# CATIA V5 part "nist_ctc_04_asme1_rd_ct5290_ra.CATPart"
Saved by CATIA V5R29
Part number: 2012_CTC_04_ASME1_V5R29_RD
Revision: D
Nomenclature: NIST PMI Test Case 4 Complex Model
Description: Complex Test Case 04 Rev C
Property "Modeled By": "Rich Eckenrode, RECON Services Incorporated - Revised by DS"
Property "CAGE Code": "64JW1"
Property "Company": "RECON Services Incorporated"
Bounding box of the stored display mesh (mm): x -250 to 250, y 0 to 780, z -134.842 to 40
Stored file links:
  E:\users\dgn\TPS V5\Import-export annotations\Step\PMI representation 2015\NIST UC\CTC\nist_ctc_04_asme1_ct5210_rd - V5R29.CATPart
  C:\Program Files\Dassault Systemes\B21\win_b64\reffiles\standard\MetricThinPitch.txt
  C:\Program Files\Dassault Systemes\B21\win_b64\reffiles\standard\MetricThickPitch.txt
  E:\users\dgn\TPS V5\Import-export annotations\Step\PMI representation 2015\NIST UC\CTC\nist_ctc_04_asme1_ct5210_rd.CATPart
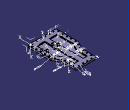
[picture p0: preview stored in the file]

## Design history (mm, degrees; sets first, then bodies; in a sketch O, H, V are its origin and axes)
TTRSSet1
AxisSystem1: origin (223.588, 25, 40), X (0, -1, 0), Y (-1, 0, 0), Z (0, 0, -1)
f4a2d38f3ddc11d3a929006094b99c4b_11 "CATTPSSet"
AxisSystem2: origin (40, 305, -40), X (0, -1, 0), Y (-1, 0, 0), Z (0, 0, -1)
AxisSystem3: origin (40, 505, -40), X (0, -1, 0), Y (-1, 0, 0), Z (0, 0, -1)
Body1 (main body)
  Sketch1 on xy-plane, origin (0, 0, 0), H (1, 0, 0), V (0, 1, 0)
    point P1 (-250, 0)
    line L1 (-250, 0) -> (250, 0)
    line L2 (250, 0) -> (250, 400)
    line L3 (175, 780) -> (-175, 780)
    line L4 (-250, 400) -> (-250, 0)
    line L5 (-175, 780) -> (-175, 530)
    line L6 (175, 780) -> (175, 530)
    point P2 (-250, 400)
    point P3 (-175, 530)
    point P6 (250, 400)
    point P9 (175, 530)
    line L7 (-250, 400) -> (-175, 530)
    line L8 (175, 530) -> (250, 400)
    distance L2 V = 250
    distance L2 L4 = 500
    distance L5 L6 = 350
    distance H P2 = 400
    distance H P6 = 400
    distance L3 P3 = 250
    distance V L6 = 175
    distance L3 P9 = 250
    distance L1 L3 = 780
    coincidence: P1 H, L4 P1, L1 P1
    horizontal: L1 H, L3 H
    vertical: L2 V, L4 V, L5 V, L6 V
  Pad1: profile Sketch1, direction (0, 0, 1), length 30
  Sketch2 on end face of Pad1, origin (0, 0, 30), H (1, 0, 0), V (0, 1, 0)
    point P1 (35, 20)
    point P2 (110, 20)
    point P3 (185, 20)
    point P4 (230, 60)
    point P5 (230, 135)
    point P6 (230, 210)
    point P7 (230, 285)
    point P8 (230, 360)
    point P9 (207, 435)
    point P10 (169, 500)
    point P11 (155, 560)
    point P12 (155, 635)
    point P13 (155, 710)
    point P14 (110, 760)
    point P15 (35, 760)
    construction line L1 (260, 20) -> (-310, 20)
    construction line L2 (290, 760) -> (-290, 760)
    construction line L3 (155, 810) -> (155, 450)
    axis line L4 (230, 400) -> (230, -60)
    point P24 (-35, 760)
    point P25 (-110, 760)
    point P26 (-155, 710)
    point P27 (-155, 635)
    point P28 (-155, 560)
    point P29 (-169, 500)
    point P30 (-207, 435)
    point P31 (-230, 360)
    point P32 (-230, 285)
    point P33 (-230, 210)
    point P34 (-230, 135)
    point P35 (-230, 60)
    point P36 (-185, 20)
    point P37 (-110, 20)
    point P38 (-35, 20)
    distance V P1 = 35
    distance V P15 = 35
    distance H L1 = 20
    distance L1 P4 = 40
    distance L1 L2 = 740
    distance V L4 = 230
    distance V L3 = 155
    distance V P2 = 110
    distance V P3 = 185
    distance L1 P5 = 115
    distance L1 P6 = 190
    distance L1 P7 = 265
    distance L1 P8 = 340
    distance L1 P9 = 415
    distance L1 P10 = 480
    distance L1 P11 = 540
    distance L1 P12 = 615
    distance L1 P13 = 690
    distance V P9 = 207
    distance V P10 = 169
    distance V P14 = 110
    horizontal: L1 H, L2 H
    coincidence: P3 L1, P2 L1, P1 L1, P14 L2, P15 L2, P11 L3, P12 L3, P13 L3, P8 L4, P7 L4, P6 L4, P5 L4, P4 L4
    vertical: L3 V, L4 V
    symmetry: P15 P24 V, P14 P25 V, P13 P26 V, P12 P27 V, P11 P28 V, P10 P29 V, P9 P30 V, P8 P31 V, P7 P32 V, P6 P33 V, P5 P34 V, P4 P35 V, P3 P36 V, P2 P37 V, P1 P38 V
  Sketch3 on end face of Pad1, origin (35, 20, 30), H (1, 0, 0), V (0, 1, 0)
    point P1 (0, 0)
    reference projected point E1 (0, 0) from Sketch2.P1
    coincidence: E1 P1
  Hole1: placed by Sketch3, at (35, 20, 30) direction (0, 0, -1), diameter 14, through (limit type 3), countersink depth 5, countersink angle 90
  UserPattern1: of Hole1, copies 30, at the points of Sketch2
  Sketch4 on end face of Pad1, origin (0, 0, 30), H (1, 0, 0), V (0, 1, 0)
    line L1 (-180, 87.702) -> (-40, 87.702)
    line L2 (-40, 87.702) -> (-40, 687.702)
    line L3 (-40, 687.702) -> (-115, 687.702)
    line L4 (-180, 379.3205) -> (-180, 87.702)
    point P4 (40, 687.702)
    line L5 (40, 687.702) -> (115, 687.702)
    line L6 (180, 379.3205) -> (180, 87.702)
    line L7 (180, 87.702) -> (40, 87.702)
    line L8 (40, 87.702) -> (40, 687.702)
    point P5 (180, 87.702)
    line L9 (-115, 687.702) -> (-115, 491.9872)
    line L10 (115, 687.702) -> (115, 491.9872)
    line L11 (115, 491.9872) -> (180, 379.3205)
    line L12 (-115, 491.9872) -> (-180, 379.3205)
    reference projected line E1 (250, 400) -> (175.0416, 529.9278) from edge [face of Pad1 from Sketch1.L8 | end face of Pad1]
    reference projected line E2 (-175.0416, 529.9278) -> (-250, 400) from edge [face of Pad1 from Sketch1.L7 | end face of Pad1]
    distance L2 L8 = 80
    distance L8 L6 = 140
    distance L2 L4 = 140
    distance L7 L5 = 600
    distance V L8 = 40
    distance H L7 = 87.702
    distance L8 L10 = 75
    distance L2 L9 = 75
    distance E1 L11 = 70.967
    distance E2 L12 = 70.967
    horizontal: L1 H, L3 H, L5 H, L7 H
    vertical: L2 V, L4 V, L6 V, L8 V, L9 V, L10 V
    coincidence: P4 L3, P5 L1
  Pocket1: profile Sketch4, direction (0, 0, -1), length 15.811
  Sketch5 on start face of Pad1, origin (0, 0, 0), H (1, 0, 0), V (0, -1, 0)
    line L1 (-195, -55) -> (195, -55)
    line L2 (195, -55) -> (195, -385.2722)
    line L3 (-195, -385.2722) -> (-195, -55)
    line L4 (-120, -725) -> (120, -725)
    line L5 (120, -725) -> (120, -515.2722)
    line L6 (-120, -515.2722) -> (-120, -725)
    line L7 (120, -515.2722) -> (195, -385.2722)
    line L8 (-120, -515.2722) -> (-195, -385.2722)
    reference intersected line E1 (250, 0) -> (250, -400) from face of Pad1 from Sketch1.L2
    reference intersected line E2 (175, -530) -> (175, -780) from face of Pad1 from Sketch1.L6
    reference intersected line E3 (-250, 0) -> (250, 0) from face of Pad1 from Sketch1.L1
    reference intersected line E4 (-250, -400) -> (-250, 0) from face of Pad1 from Sketch1.L4
    reference intersected line E5 (-175, -780) -> (-175, -530) from face of Pad1 from Sketch1.L5
    reference intersected line E6 (175, -780) -> (-175, -780) from face of Pad1 from Sketch1.L3
    reference intersected line E7 (250, -400) -> (175.0416, -529.9278) from face of Pad1 from Sketch1.L8
    reference intersected line E8 (-175.0416, -529.9278) -> (-250, -400) from face of Pad1 from Sketch1.L7
    distance E1 L2 = 55
    distance E2 L5 = 55
    distance E3 L1 = 55
    distance E4 L3 = 55
    distance E5 L6 = 55
    distance E6 L4 = 55
    distance E7 L7 = 55
    distance E8 L8 = 55
    horizontal: L1 H, L4 H
    vertical: L2 V, L3 V, L5 V, L6 V
  Pad2: profile Sketch5, direction (0, 0, -1), length 40
  Sketch6 on end face of Pad2, origin (0, 0, -40), H (1, 0, 0), V (0, -1, 0)
    line L1 (-40, -655) -> (40, -655)
    line L2 (40, -655) -> (40, -505)
    line L3 (40, -505) -> (-40, -505)
    line L4 (-40, -505) -> (-40, -655)
    point P5 (-40, -455)
    line L5 (-40, -455) -> (40, -455)
    line L6 (40, -455) -> (40, -305)
    line L7 (40, -305) -> (-40, -305)
    line L8 (-40, -305) -> (-40, -455)
    point P7 (40, -305)
    reference intersected line E1 (-195, -55) -> (195, -55) from face of Pad2 from Sketch5.L1
    axis line L9 (0, -70) -> (0, -700)
    point P9 (0, -70)
    distance L3 L1 = 150
    distance L5 L7 = 150
    distance L3 L5 = 50
    distance E1 L7 = 250
    distance L4 L2 = 80
    distance L9 L8 = 40
    horizontal: L1 H, L3 H, L5 H, L7 H
    vertical: L2 V, L4 V, L6 V, L8 V, L9 V
    coincidence: P5 L4, P7 L2, P9 V
  Pad3: profile Sketch6, direction (0, 0, -1), length 50
  Sketch7 on face of Pad3 from Sketch6.L7, origin (0, 305, 0), H (1, 0, 0), V (0, 0, 1)
    arc A1 centre (0, -65) radius 12.5 from (12.5, -65) to (-12.5, -65) ccw
    point P1 (0, -65)
    reference intersected line E1 (40, -90) -> (-40, -90) from end face of Pad3
    line L1 (12.5, -103.8824) -> (12.5, -65)
    line L2 (-12.5, -103.8824) -> (-12.5, -65)
    line L3 (-12.5, -103.8824) -> (12.5, -103.8824)
    radius A1 = 12.5
    distance V P1 = 0
    distance E1 P1 = 25
    vertical: L1 V, L2 V
    tangency: A1 L1, L2 A1
    horizontal: L3 H
  Pocket2: profile Sketch7, direction (0, 1, 0), through (limit type 3)
  Sketch8 on end face of Pad2, origin (0, 0, -40), H (1, 0, 0), V (0, -1, 0)
    line L1 (-25, -40) -> (25, -40)
    line L2 (25, -40) -> (25, -205)
    line L3 (-25, -205) -> (-25, -40)
    axis line L4 (0, -20) -> (0, -280)
    point P3 (0, -20)
    arc A1 centre (0, -205) radius 25 from (-25, -205) to (25, -205) ccw
    point P5 (0, -205)
    reference intersected line E1 (-195, -55) -> (195, -55) from face of Pad2 from Sketch5.L1
    reference intersected line E2 (-195, -55) -> (195, -55) from face of Pad2 from Sketch5.L1
    distance L2 L3 = 50
    distance L4 L3 = 25
    distance E1 P5 = 150
    distance E2 L1 = 15
    horizontal: L1 H
    vertical: L2 V, L3 V, L4 V
    coincidence: P3 V
    tangency: A1 L3, A1 L2
  Pocket3: profile Sketch8, direction (0, 0, 1), length 25.125
  Sketch9 on end face of Pad2, origin (0, 0, -40), H (1, 0, 0), V (0, -1, 0)
    line L1 (-154, -273) -> (-79, -273)
    line L2 (-79, -273) -> (-79, -338)
    line L3 (-154, -338) -> (-154, -273)
    line L4 (-101, -403) -> (-132, -403)
    point P5 (-101, -403)
    axis line L5 (0, 20) -> (0, -690)
    point P7 (0, 20)
    reference intersected line E1 (-195, -55) -> (195, -55) from face of Pad2 from Sketch5.L1
    line L6 (-79, -338) -> (-101, -403)
    line L7 (-154, -338) -> (-132, -403)
    reference intersected line E2 (-40, -455) -> (-40, -305) from face of Pad3 from Sketch6.L8
    distance L3 L2 = 75
    distance L1 L4 = 130
    length L2 = 65
    length L4 = 31
    distance P5 L2 = 22
    distance E1 L1 = 218
    length L3 = 65
    distance E2 L2 = 39
    horizontal: L1 H, L4 H
    vertical: L2 V, L3 V, L5 V
    coincidence: P7 V
  Pocket4: profile Sketch9, direction (0, 0, 1), length 26.25
  Sketch10 on end face of Pad2, origin (0, 0, -40), H (1, 0, 0), V (0, -1, 0)
    line L1 (-65, -225) -> (-125, -225)
    line L2 (-125, -225) -> (-125, -105)
    construction line L3 (-125, -75) -> (-65, -75)
    line L4 (-65, -105) -> (-65, -225)
    point P3 (-125, -75)
    point P4 (-65, -75)
    arc A1 centre (-95, -105) radius 30 from (-65, -105) to (-125, -105) ccw
    distance L4 L2 = 60
    distance V L4 = 65
    length L4 = 120
    length L2 = 120
    distance H L1 = 225
    horizontal: L1 H, L3 H
    vertical: L2 V, L4 V
    tangency: A1 L4, A1 L3, A1 L2
    coincidence: P4 L4, P3 L2
  Pad4: profile Sketch10, direction (0, 0, -1), length 65
  Sketch11 on face of Pad4 from Sketch10.L4, origin (-65, 0, 0), H (0, 1, 0), V (0, 0, 1)
    projected line E1 (225, -40) -> (225, -105) from edge [face of Pad4 from Sketch10.L4 | face of Pad4 from Sketch10.L1]
    projected line E2 (225, -40) -> (225, -121.9635) from edge [face of Pad4 from Sketch10.L4 | face of Pad4 from Sketch10.L1]
    line L1 (225, -121.9635) -> (22.1331, -121.9635)
    line L2 (225, -40) -> (22.1331, -121.9635)
    angle E1 L2 = 68
    horizontal: L1 H
  Pocket5: profile Sketch11, direction (-1, 0, 0), through (limit type 3)
  Mirror1: of Pocket4, Pad4, Pocket5, about yz-plane
  Sketch12 on end face of Pad3, origin (0, 0, -90), H (1, 0, 0), V (0, -1, 0)
    point P1 (-26.25, -625)
    point P2 (-26.25, -580)
    point P3 (-26.25, -535)
    point P4 (26.25, -535)
    point P5 (26.25, -580)
    point P6 (26.25, -625)
    construction line L1 (26.25, -270.0818) -> (26.25, -700)
    construction line L2 (-26.25, -280.7673) -> (-26.25, -700)
    construction line L3 (70, -580) -> (-70, -580)
    construction line L4 (-70, -535) -> (70, -535)
    construction line L5 (70, -425) -> (-70, -425)
    construction line L6 (-70, -380) -> (70, -380)
    construction line L7 (70, -335) -> (-70, -335)
    axis line L8 (70, -625) -> (-70, -625)
    reference intersected line E1 (40, -655) -> (-40, -655) from face of Pad3 from Sketch6.L1
    reference intersected line E2 (-40, -655) -> (-40, -505) from face of Pad3 from Sketch6.L4
    point P23 (26.25, -425)
    point P24 (26.25, -380)
    point P25 (26.25, -335)
    point P26 (-26.25, -335)
    point P27 (-26.25, -380)
    point P28 (-26.25, -425)
    distance L7 L6 = 45
    distance L6 L5 = 45
    distance L4 L3 = 45
    distance L3 L8 = 45
    distance L4 L5 = 110
    distance E1 L8 = 30
    distance L1 L2 = 52.5
    distance E2 L2 = 13.75
    vertical: L1 V, L2 V
    horizontal: L3 H, L4 H, L5 H, L6 H, L7 H, L8 H
    coincidence: P4 L4, P4 L1, P5 L3, P5 L1, P6 L8, P6 L1, P1 L2, P1 L8, P2 L3, P2 L2, P3 L2, P3 L4, P23 L5, P23 L1, P24 L6, P24 L1, P25 L7, P25 L1, P26 L7, P26 L2, P27 L6, P27 L2, P28 L5, P28 L2
  Sketch13 on end face of Pad3, origin (-30.5843, 356.3583, -90), H (1, 0, 0), V (0, -1, 0)
    point P1 (4.3343, -268.6417)
    reference intersected line E1 (-9.4157, -98.6417) -> (-9.4157, 51.3583) from face of Pad3 from Sketch6.L8
    reference intersected line E2 (70.5843, -298.6417) -> (-9.4157, -298.6417) from face of Pad3 from Sketch6.L1
    distance E1 P1 = 13.75
    distance E2 P1 = 30
  Hole2: placed by Sketch13, at (-26.25, 625, -90) direction (0, 0, 1), diameter 6.65, depth 25, V-bottom angle 118, threaded, thread diameter 8, thread depth 20, pitch 1.25
  UserPattern2: of Hole2, copies 12, at the points of Sketch12
  Sketch14 on start face of Pad1, origin (-146.4941, 751.3979, 0), H (1, 0, 0), V (0, -1, 0)
    point P1 (-2.0939, -0.6971)
    reference intersected line E1 through (146.4941, 0) direction (0, 1) from yz-plane
    reference intersected line E2 (-103.5059, 751.3979) -> (396.4941, 751.3979) from face of Pad1 from Sketch1.L1
    distance E1 P1 = 148.588
    distance E2 P1 = 752.095
  Hole3: placed by Sketch14, at (-148.588, 752.095, 0) direction (0, 0, 1), diameter 12.1, depth 15, V-bottom angle 118
  Sketch15 on face of Pad3 from Sketch6.L4, origin (-40, 616.5945, -70.4727), H (0, 1, 0), V (0, 0, -1)
    point P1 (-14.0945, 7.5273)
    reference projected line E1 (38.4055, -30.4727) -> (38.4055, 19.5273) from edge [face of Pad3 from Sketch6.L1 | face of Pad3 from Sketch6.L4]
    reference projected line E2 (-111.5945, 19.5273) -> (38.4055, 19.5273) from edge [face of Pad3 from Sketch6.L4 | end face of Pad3]
    distance E1 P1 = 52.5
    distance P1 E2 = 12
  Hole4: placed by Sketch15, at (-40, 602.5, -78) direction (1, 0, 0), diameter 10, through (limit type 3)
  RectPattern1: of Hole4, direction 1 instances 2, spacing 200, along edge [face of Pad3 from Sketch6.L8 | end face of Pad3] reversed, direction 2 instances 2, spacing 190
  Sketch16 on face of Pocket5 from Sketch11.L2, origin (-96.1933, 110.3154, -86.3356), H (1, 0, 0), V (0, -0.9272, -0.3746)
    point P1 (1.1933, 5.7328)
    reference projected line E2 (-28.8067, -123.6913) -> (-28.8067, 5.7328) from edge [face of Pocket5 from Sketch11.L2 | face of Pad4 from Sketch10.L2]
    construction line L1 (31.1933, 5.7328) -> (-28.8067, 5.7328)
    distance E2 P1 = 30
    distance P1 L1 = 0
    horizontal: L1 H
  Hole5: placed by Sketch16, at (-95, 105, -88.4831) direction (0, -0.3746, 0.9272), diameter 10.2, depth 30, V-bottom angle 118, threaded, thread diameter 12, thread depth 25, pitch 1.75
  RectPattern2: of Hole5, direction 1 instances 2, spacing 95, along edge [face of Pocket5 from Sketch11.L2 | face of Pad4 from Sketch10.L2] reversed, direction 2 instances 2, spacing 190, along edge [face of Pad2 from Sketch5.L1 | end face of Pad2] reversed
  Sketch17 on face of Pocket5 from Sketch11.L2, origin (-93.6782, 140.5967, -74.1011), H (1, 0, 0), V (0, -0.9272, -0.3746)
    point P1 (-1.3218, 8.3923)
    reference projected line E2 (-31.3218, -91.0318) -> (-31.3218, 38.3923) from edge [face of Pocket5 from Sketch11.L2 | face of Pad4 from Sketch10.L2]
    construction line L1 (28.6782, 38.3923) -> (-31.3218, 38.3923)
    distance P1 L1 = 30
    distance P1 E2 = 30
    horizontal: L1 H
  Hole6: placed by Sketch17, at (-95, 132.8155, -77.2449) direction (0, -0.3746, 0.9272), diameter 12, depth 40, V-bottom angle 118, counterbore diameter 20, counterbore depth 20
  RectPattern3: of Hole6, direction 1 instances 2, spacing 35, along edge [face of Pocket5 from Sketch11.L2 | face of Pad4 from Sketch10.L2] reversed, direction 2 instances 2, spacing 190, along edge [face of Pad2 from Sketch5.L1 | end face of Pad2] reversed
  Fillet1: radius 25, on edge [face of Pad1 from Sketch1.L1 | face of Pad1 from Sketch1.L4]; edge [face of Pad1 from Sketch1.L2 | face of Pad1 from Sketch1.L1]; edge [face of Pad1 from Sketch1.L4 | face of Pad1 from Sketch1.L7]; edge [face of Pad1 from Sketch1.L7 | face of Pad1 from Sketch1.L5]; edge [face of Pad1 from Sketch1.L5 | face of Pad1 from Sketch1.L3]; edge [face of Pad1 from Sketch1.L3 | face of Pad1 from Sketch1.L6]; edge [face of Pad1 from Sketch1.L6 | face of Pad1 from Sketch1.L8]; edge [face of Pad1 from Sketch1.L8 | face of Pad1 from Sketch1.L2]
  Sketch18 on start face of Pad1, origin (226.2623, 27.9824, 0), H (1, 0, 0), V (0, -1, 0)
    point P1 (-2.6743, 2.9824)
    reference intersected line E1 through (-226.2623, 0) direction (0, 1) from yz-plane
    reference intersected line E2 through (0, 27.9824) direction (1, 0) from zx-plane
    distance E1 P1 = 223.588
    distance E2 P1 = 25
  Hole7: placed by Sketch18, at (223.588, 25, 0) direction (0, 0, 1), diameter 12.1, depth 15, V-bottom angle 118
  Fillet2: radius 13, on edge [face of Pad2 from Sketch5.L5 | face of Pad2 from Sketch5.L4]; edge [face of Pad2 from Sketch5.L4 | face of Pad2 from Sketch5.L6]; edge [face of Pad2 from Sketch5.L7 | face of Pad2 from Sketch5.L5]; edge [face of Pad2 from Sketch5.L2 | face of Pad2 from Sketch5.L7]; edge [face of Pad2 from Sketch5.L1 | face of Pad2 from Sketch5.L2]; edge [face of Pad2 from Sketch5.L3 | face of Pad2 from Sketch5.L1]; edge [face of Pad2 from Sketch5.L8 | face of Pad2 from Sketch5.L3]; edge [face of Pad2 from Sketch5.L6 | face of Pad2 from Sketch5.L8]
  Fillet3: radius 5, on edge [start face of Pad1 | face of Pad2 from Sketch5.L5]; edge [face of Pad2 from Sketch5.L5 | end face of Pad2]
  Fillet4: radius 2.5, on edge [face of Pocket3 from Sketch8.L3 | end face of Pocket3]
  Fillet5: radius 4, on edge [face of Pad3 from Sketch6.L1 | face of Pad3 from Sketch6.L4]; edge [face of Pad3 from Sketch6.L2 | face of Pad3 from Sketch6.L1]; edge [face of Pad3 from Sketch6.L4 | face of Pad3 from Sketch6.L3]; edge [face of Pad3 from Sketch6.L3 | face of Pad3 from Sketch6.L2]; edge [face of Pad3 from Sketch6.L6 | face of Pad3 from Sketch6.L5]; edge [face of Pad3 from Sketch6.L5 | face of Pad3 from Sketch6.L8]; edge [face of Pad3 from Sketch6.L7 | face of Pad3 from Sketch6.L6]; edge [face of Pad3 from Sketch6.L8 | face of Pad3 from Sketch6.L7]
  Fillet6: radius 4, on edge [end face of Pad2 | face of Pad3 from Sketch6.L4]; edge [end face of Pad2 | face of Pad3 from Sketch6.L8]
  Fillet7: radius 5, on end face of Pocket1 (x2); edge [face of Pocket1 from Sketch4.L1 | face of Pocket1 from Sketch4.L4]; edge [face of Pocket1 from Sketch4.L7 | face of Pocket1 from Sketch4.L8]; edge [face of Pocket1 from Sketch4.L4 | face of Pocket1 from Sketch4.L12]; edge [face of Pocket1 from Sketch4.L12 | face of Pocket1 from Sketch4.L9]; edge [face of Pocket1 from Sketch4.L6 | face of Pocket1 from Sketch4.L7]; edge [face of Pocket1 from Sketch4.L2 | face of Pocket1 from Sketch4.L1]; edge [face of Pocket1 from Sketch4.L11 | face of Pocket1 from Sketch4.L6]; edge [face of Pocket1 from Sketch4.L10 | face of Pocket1 from Sketch4.L11]; edge [face of Pocket1 from Sketch4.L5 | face of Pocket1 from Sketch4.L10]; edge [face of Pocket1 from Sketch4.L3 | face of Pocket1 from Sketch4.L2]; edge [face of Pocket1 from Sketch4.L8 | face of Pocket1 from Sketch4.L5]; edge [face of Pocket1 from Sketch4.L9 | face of Pocket1 from Sketch4.L3]
  Fillet8: radius 5, on edge [face of Mirror1 | end face of Pad2]; edge [end face of Pad2 | face of Pad4 from Sketch10.L4]; face of Mirror1; end face of Pocket4; edge [face of Pocket4 from Sketch9.L7 | face of Pocket4 from Sketch9.L3]; edge [face of Pocket4 from Sketch9.L4 | face of Pocket4 from Sketch9.L7]; edge [face of Mirror1 | face of Mirror1] (x6); edge [face of Pocket4 from Sketch9.L6 | face of Pocket4 from Sketch9.L4]; edge [face of Pocket4 from Sketch9.L2 | face of Pocket4 from Sketch9.L6]; edge [face of Pocket4 from Sketch9.L1 | face of Pocket4 from Sketch9.L2]; edge [face of Pocket4 from Sketch9.L3 | face of Pocket4 from Sketch9.L1]
  Chamfer1: length 5, second length 5, on edge [end face of Pad2 | face of Pocket4 from Sketch9.L1]; edge [face of Mirror1 | end face of Pad2]
  Plane1: type Angle, RefPlane face of Pocket5 from Sketch11.L2, Direction edge [face of Pocket5 from Sketch11.L2 | end face of Pad2], Angle 90
  Sketch19 on face of Mirror1, origin (0, 0, -13.75), H (1, 0, 0), V (0, -1, 0)
    circle A1 centre (115, -330) radius 17.5
    point P1 (115, -330)
    distance H P1 = 330
    distance V P1 = 115
    radius A1 = 17.5
  Point1: (223.588, 25, 40)
  Fill1: Boundary Sketch19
